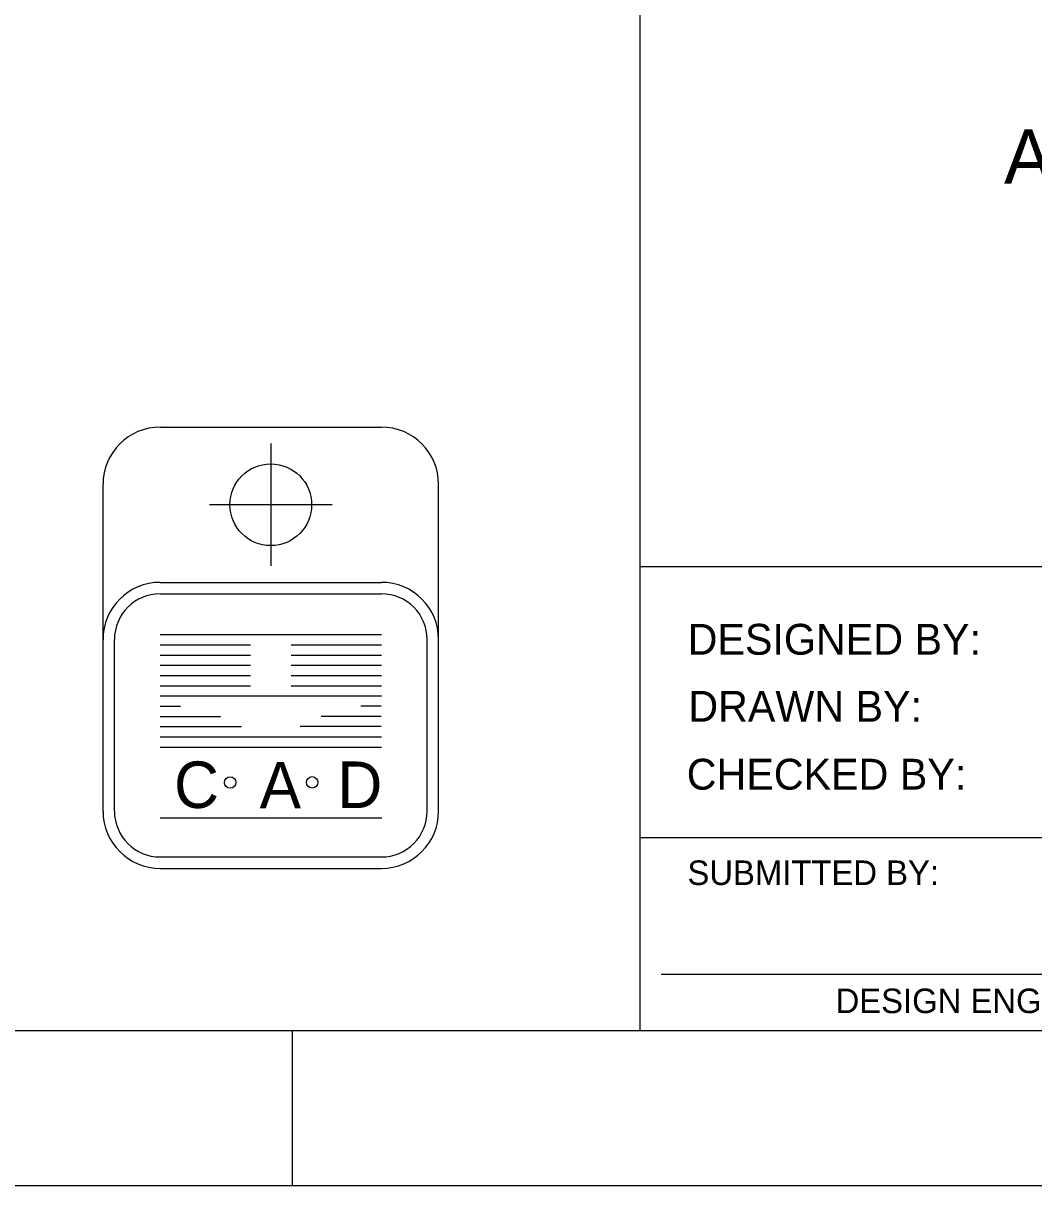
# Model space of a CAD drawing. Extents: x 0.1 to 13.5, y 0.1 to 9.5.
# Drawn here: x 10.461 to 11.549, y 0.125 to 1.377 of the extents above; entities that cross this region are included whole.
import ezdxf

# ---------------------------------------------------------------- set-up
doc = ezdxf.new("R2010")
doc.units = 0
doc.layers.add('Level 1', color=7, linetype='Continuous')
doc.layers.add('Level 2', color=7, linetype='Continuous')

msp = doc.modelspace()

# ---------------------------------------------------------------- linework, layer by layer
at = {"layer": 'Level 1'}
for p, q in [((11.125, 0.2917), (11.125, 1.875)), ((10.608, 0.942), (10.8462, 0.942)), ((10.7271, 0.9245), (10.7271, 0.7925)), ((10.5464, 0.5284), (10.5464, 0.8805)), ((10.9078, 0.5284), (10.9078, 0.8805)), ((10.6611, 0.8585), (10.7931, 0.8585)), ((13.2917, 0.7917), (11.125, 0.7917)), ((10.608, 0.7748), (10.8462, 0.7748)), ((10.608, 0.7625), (10.8462, 0.7625)), ((10.608, 0.7185), (10.8462, 0.7185)), ((10.5587, 0.5284), (10.5587, 0.7133)), ((10.608, 0.7075), (10.7051, 0.7075)), ((10.7491, 0.7075), (10.8462, 0.7075)), ((10.8955, 0.5284), (10.8955, 0.7133)), ((10.608, 0.6965), (10.7051, 0.6965)), ((10.7491, 0.6965), (10.8462, 0.6965)), ((10.608, 0.6855), (10.7051, 0.6855)), ((10.7491, 0.6855), (10.8462, 0.6855)), ((10.608, 0.6745), (10.7051, 0.6745)), ((10.7491, 0.6745), (10.8462, 0.6745)), ((10.608, 0.6635), (10.7051, 0.6635)), ((10.608, 0.6525), (10.8462, 0.6525)), ((10.7491, 0.6635), (10.8462, 0.6635)), ((10.608, 0.6415), (10.63, 0.6415)), ((10.8461, 0.6415), (10.8241, 0.6415)), ((10.608, 0.6305), (10.6729, 0.6305)), ((10.8461, 0.6305), (10.7813, 0.6305)), ((10.608, 0.6195), (10.6954, 0.6195)), ((10.8461, 0.6195), (10.7587, 0.6195)), ((10.608, 0.6085), (10.8462, 0.6085)), ((10.608, 0.5975), (10.8462, 0.5975)), ((10.608, 0.5211), (10.8466, 0.5211)), ((11.125, 0.5), (11.875, 0.5)), ((10.608, 0.4791), (10.8462, 0.4791)), ((10.608, 0.4668), (10.8462, 0.4668)), ((11.1474, 0.3528), (11.8484, 0.3528)), ((10.75, 0.2917), (10.75, 0.125))]:
    msp.add_line(p, q, dxfattribs=at)
for points in [[(0.125, 9.4583), (13.4583, 9.4583), (13.4583, 0.125), (0.125, 0.125)], [(0.625, 9.2917), (13.2917, 9.2917), (13.2917, 0.2917), (0.625, 0.2917)]]:
    msp.add_lwpolyline(points, close=True, dxfattribs=at)
for centre, radius in [((10.7271, 0.8584), 0.044), ((10.6834, 0.5593), 0.00616), ((10.7716, 0.5594), 0.00616)]:
    msp.add_circle(centre, radius, dxfattribs=at)
for centre, radius, start, end in [((10.608, 0.8804), 0.0616, 90, 180), ((10.8462, 0.8804), 0.0616, 0, 90), ((10.608, 0.7132), 0.0616, 90, 180), ((10.8462, 0.7132), 0.0616, 0, 90), ((10.608, 0.7132), 0.0493, 90, 180), ((10.8462, 0.7132), 0.0493, 0, 90), ((10.608, 0.5284), 0.0616, 180, 270), ((10.608, 0.5284), 0.0493, 180, 270), ((10.8462, 0.5284), 0.0616, 270, 360), ((10.8462, 0.5284), 0.0493, 270, 360)]:
    msp.add_arc(centre, radius, start, end, dxfattribs=at)

# ---------------------------------------------------------------- texts
for s, height, p in [('DESIGNED BY:', 0.033208, (11.176, 0.6969)), ('DRAWN BY:', 0.03321, (11.1767, 0.6247)), ('C', 0.0501, (10.6229, 0.5318)), ('A', 0.0501, (10.715, 0.5314)), ('D', 0.0501, (10.7988, 0.5318)), ('CHECKED BY:', 0.033208, (11.175, 0.5516)), ('SUBMITTED BY:', 0.026417, (11.1758, 0.4489)), ('DESIGN ENGINEER', 0.026417, (11.3353, 0.3109))]:
    msp.add_text(s, height=height, dxfattribs=at).set_placement(p)
at = {"layer": 'Level 2'}
msp.add_text('AND HWY. 45 LEVEE CLOSURES', height=0.058417, dxfattribs=at).set_placement((11.5167, 1.2041))

doc.saveas('drawing.dxf')
